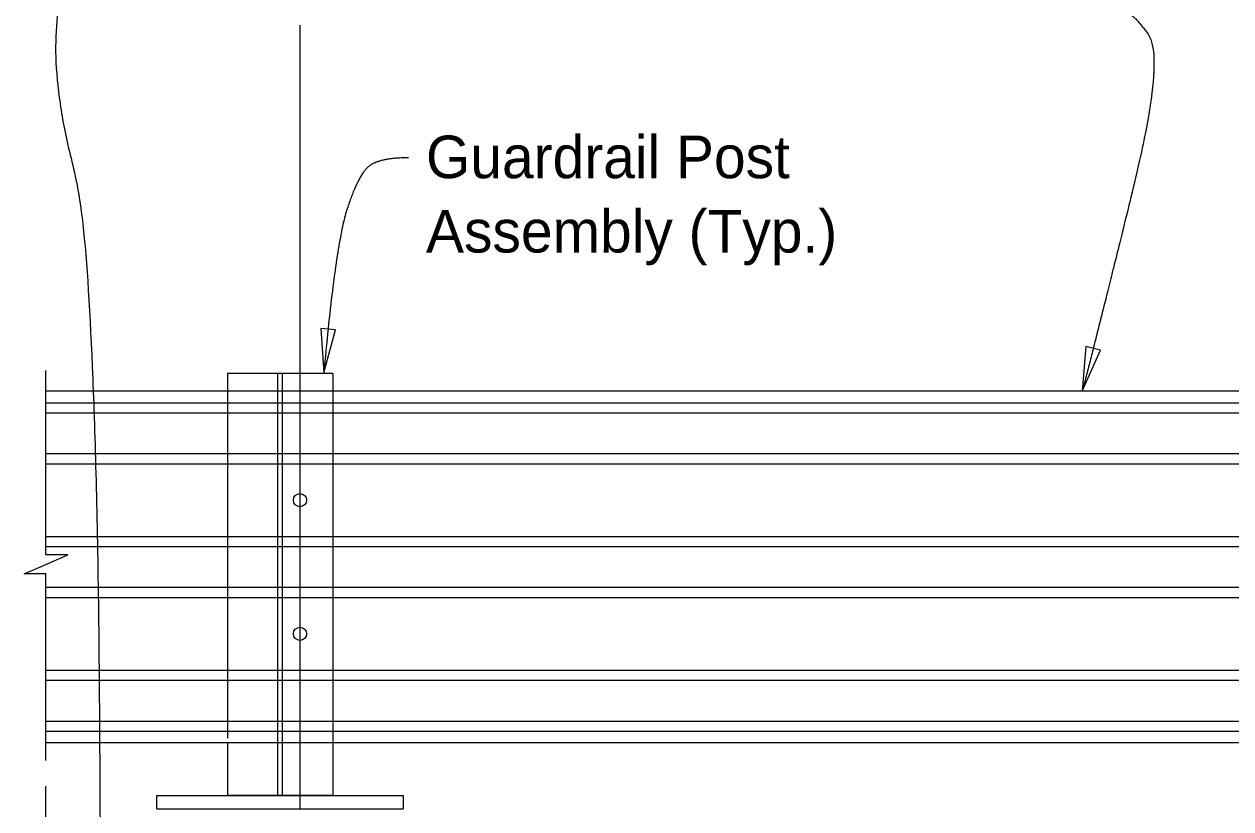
# Model space of a CAD drawing. Extents: x 21526.6 to 21595.9, y 56117 to 56157.3.
# Drawn here: x 21527.14 to 21532.85, y 56135.21 to 56138.93 of the extents above; entities that cross this region are included whole.
import ezdxf

# ---------------------------------------------------------------- set-up
doc = ezdxf.new("R2010")
doc.units = 0
for name, color, linetype in [('Patterning', 7, 'Continuous'), ('PlotBorder_dp', 7, 'Continuous'), ('SheetBorder_dp', 7, 'Continuous'), ('TextMisc', 7, 'Continuous')]:
    doc.layers.add(name, color=color, linetype=linetype)

msp = doc.modelspace()

# ---------------------------------------------------------------- linework, layer by layer
at = {"layer": 'Patterning'}
msp.add_line((21528.4455, 56138.9228), (21528.4455, 56135.2123), dxfattribs=at)
at = {"layer": 'PlotBorder_dp'}
for points in [[(21528.5583, 56137.2748), (21528.614, 56137.4786), (21528.5438, 56137.4856)], [(21532.1507, 56137.1892), (21532.2363, 56137.3823), (21532.1679, 56137.3997)]]:
    msp.add_lwpolyline(points, close=True, dxfattribs=at)
for points in [[(21527.2427, 56135.4395), (21527.2427, 56136.3228), (21527.1393, 56136.3228), (21527.2427, 56136.3678), (21527.346, 56136.4128), (21527.2427, 56136.4128), (21527.2427, 56137.2857)], [(21527.2427, 56134.3351), (21527.2427, 56134.9021), (21527.1393, 56134.9021), (21527.2427, 56134.9471), (21527.346, 56134.9921), (21527.2427, 56134.9921), (21527.2427, 56135.3182)]]:
    msp.add_lwpolyline(points, dxfattribs=at)
for points in [[(21527.5433, 56139.7972), (21527.186, 56139.7968), (21527.352, 56139.3409), (21527.253, 56138.6974), (21527.5005, 56137.7639), (21527.5005, 56134.6471)], [(21532.1515, 56138.9888), (21532.2823, 56138.9888), (21532.3882, 56138.9888), (21532.5399, 56138.7618), (21532.2472, 56137.5615), (21532.1507, 56137.1892)], [(21528.9594, 56138.2938), (21528.8192, 56138.2938), (21528.7196, 56138.2097), (21528.6137, 56137.8793), (21528.5583, 56137.2748)]]:
    msp.add_open_spline(points, degree=2, dxfattribs=at)
at = {"layer": 'SheetBorder_dp'}
for p, q in [((21528.3413, 56135.2726), (21528.3413, 56137.2726)), ((21528.3622, 56135.2726), (21528.3622, 56137.2726)), ((21528.1017, 56137.1892), (21528.1017, 56135.5456)), ((21528.6017, 56137.1892), (21528.6017, 56135.5225))]:
    msp.add_line(p, q, dxfattribs=at)
at = {"layer": 'TextMisc'}
for p, q in [((21528.6017, 56137.2726), (21528.1017, 56137.2726)), ((21528.1017, 56137.2726), (21528.1017, 56137.1892)), ((21528.6017, 56137.2726), (21528.6017, 56137.1892)), ((21534.2788, 56137.1892), (21527.2426, 56137.1892)), ((21527.2426, 56137.1336), (21534.2788, 56137.1336)), ((21527.2426, 56137.0854), (21534.2788, 56137.0854)), ((21527.2426, 56136.8926), (21534.2788, 56136.8926)), ((21527.2426, 56136.8444), (21534.2788, 56136.8444)), ((21527.2426, 56136.5004), (21534.2788, 56136.5004)), ((21527.2426, 56136.4522), (21534.2788, 56136.4522)), ((21527.2426, 56136.2594), (21534.2788, 56136.2594)), ((21527.2426, 56136.2112), (21534.2788, 56136.2112)), ((21527.2426, 56135.8673), (21534.2788, 56135.8673)), ((21527.2426, 56135.8191), (21534.2788, 56135.8191)), ((21527.2426, 56135.6262), (21534.2788, 56135.6262)), ((21527.2426, 56135.578), (21534.2788, 56135.578)), ((21534.2788, 56135.5225), (21527.2426, 56135.5225)), ((21528.1017, 56135.5225), (21528.1017, 56135.2726)), ((21528.6017, 56135.5225), (21528.6017, 56135.2726)), ((21528.6017, 56135.4392), (21528.6017, 56135.2726)), ((21527.7684, 56135.2726), (21528.9351, 56135.2726)), ((21527.7684, 56135.2101), (21527.7684, 56135.2726)), ((21528.6017, 56135.2726), (21528.1017, 56135.2726)), ((21528.1017, 56135.2726), (21528.6017, 56135.2726)), ((21528.9351, 56135.2726), (21528.9351, 56135.2101)), ((21527.7684, 56135.2101), (21528.9351, 56135.2101))]:
    msp.add_line(p, q, dxfattribs=at)
for centre in [(21528.4455, 56136.6725), (21528.4455, 56136.0393)]:
    msp.add_circle(centre, 0.0312, dxfattribs=at)

# ---------------------------------------------------------------- texts
at = {"layer": 'PlotBorder_dp'}
for s, p in [('Guardrail Post ', (21529.0427, 56138.1973)), ('Assembly (Typ.)', (21529.0427, 56137.8453))]:
    msp.add_text(s, height=0.2016, dxfattribs=at).set_placement(p)

doc.saveas('drawing.dxf')
